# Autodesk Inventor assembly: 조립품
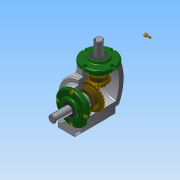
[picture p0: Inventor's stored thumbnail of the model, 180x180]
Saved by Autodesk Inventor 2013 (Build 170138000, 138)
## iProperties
Created: 2017-04
Part Number: 조립품
Document SubType Name: Assembly
Designer: MR
Author: MR
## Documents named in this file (14)
- C:\Users\MR\Desktop\470408V1003\조립품.iam
- C:\Users\MR\Desktop\470408V1003\본체.ipt
- C:\Users\MR\Desktop\470408V1003\메인 베벨기어.ipt
- C:\Users\MR\Desktop\470408V1003\메인 축.ipt
- 메인 축.ipt
- C:\Users\MR\Desktop\470408V1003\키 5x5.ipt
- C:\Users\MR\Desktop\470408V1003\베어링 6203.ipt
- C:\Users\MR\Desktop\470408V1003\볼트 M4.ipt
- C:\Users\MR\Desktop\470408V1003\오일실 17 32 8.ipt
- C:\Users\MR\Desktop\470408V1003\커버.ipt
- C:\Users\MR\Desktop\470408V1003\서브 베벨기어.ipt
- C:\Users\MR\Desktop\470408V1003\서브 축.ipt
- 서브 축.ipt
- C:\Users\MR\Desktop\470408V1003\키 4x4.ipt
